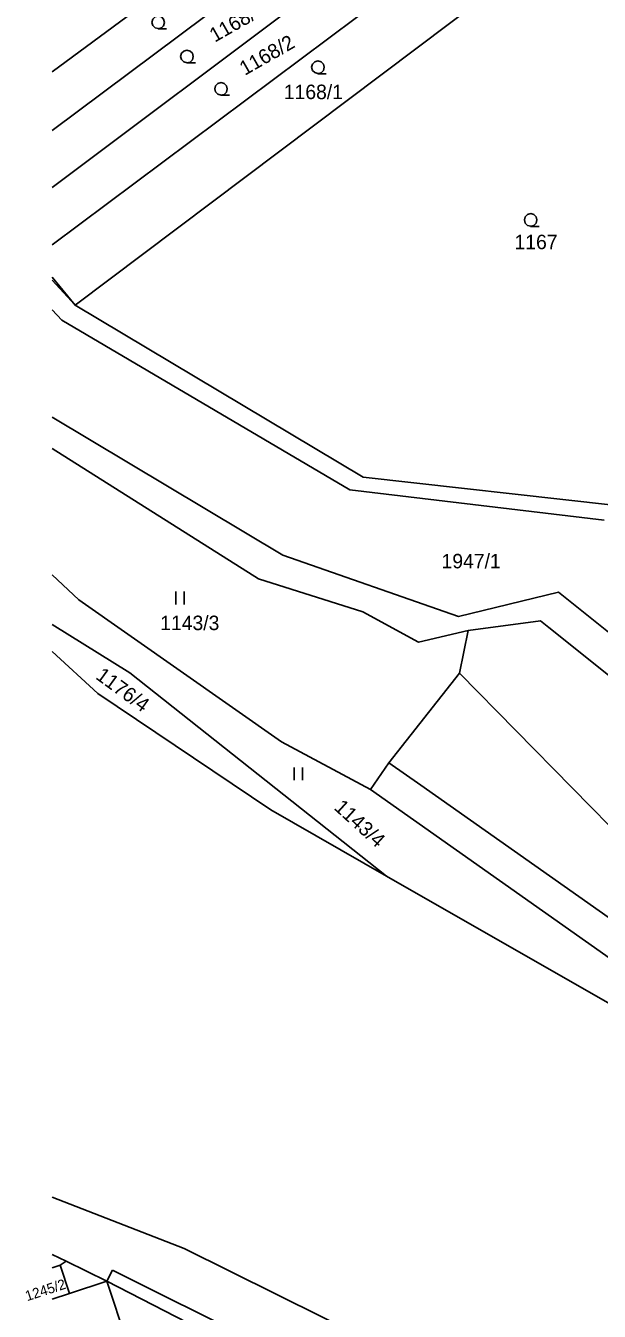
# Model space of a CAD drawing. Extents: x -621797 to -620972, y -1175539 to -1174697.
# Drawn here: x -621793.4 to -621726, y -1175130.5 to -1174979.5 of the extents above; entities that cross this region are included whole.
import ezdxf

# ---------------------------------------------------------------- set-up
doc = ezdxf.new("R2010")
doc.units = 0
for name, color, linetype in [('INZ mimo EON - nadz', 7, 'Continuous'), ('SDEL EON', 7, 'Continuous'), ('SDEL EON - popis', 7, 'Continuous'), ('Silnoproud EON', 7, 'Continuous'), ('Silnoproud EON - popis', 7, 'Continuous')]:
    doc.layers.add(name, color=color, linetype=linetype)

msp = doc.modelspace()

# ---------------------------------------------------------------- linework, layer by layer
at = {"layer": 'SDEL EON'}
for p, q in [((-621775.79, -1175045.98), (-621775.79, -1175047.48)), ((-621774.79, -1175047.48), (-621774.79, -1175045.98)), ((-621761.88, -1175066.65), (-621761.88, -1175068.15)), ((-621760.88, -1175068.15), (-621760.88, -1175066.65))]:
    msp.add_line(p, q, dxfattribs=at)
for points in [[(-621777.85, -1174979.84), (-621778.23, -1174979.74), (-621778.5, -1174979.47), (-621778.6, -1174979.1), (-621778.5, -1174978.73), (-621778.23, -1174978.46), (-621777.86, -1174978.36), (-621777.49, -1174978.46), (-621777.22, -1174978.73), (-621777.12, -1174979.11), (-621777.22, -1174979.49), (-621777.49, -1174979.76), (-621777.87, -1174979.86), (-621776.87, -1174979.86)], [(-621774.47, -1174983.85), (-621774.85, -1174983.75), (-621775.12, -1174983.48), (-621775.22, -1174983.11), (-621775.12, -1174982.74), (-621774.85, -1174982.47), (-621774.48, -1174982.37), (-621774.11, -1174982.47), (-621773.84, -1174982.74), (-621773.74, -1174983.12), (-621773.84, -1174983.5), (-621774.11, -1174983.77), (-621774.49, -1174983.87), (-621773.49, -1174983.87)], [(-621759.07, -1174985.11), (-621759.45, -1174985.01), (-621759.72, -1174984.74), (-621759.82, -1174984.37), (-621759.72, -1174984), (-621759.45, -1174983.73), (-621759.08, -1174983.63), (-621758.71, -1174983.73), (-621758.44, -1174984), (-621758.34, -1174984.38), (-621758.44, -1174984.76), (-621758.71, -1174985.03), (-621759.09, -1174985.13), (-621758.09, -1174985.13)], [(-621770.46, -1174987.65), (-621770.84, -1174987.55), (-621771.11, -1174987.28), (-621771.21, -1174986.91), (-621771.11, -1174986.54), (-621770.84, -1174986.27), (-621770.47, -1174986.17), (-621770.1, -1174986.27), (-621769.83, -1174986.54), (-621769.73, -1174986.92), (-621769.83, -1174987.3), (-621770.1, -1174987.57), (-621770.48, -1174987.67), (-621769.48, -1174987.67)], [(-621734.05, -1175003.05), (-621734.43, -1175002.95), (-621734.7, -1175002.68), (-621734.8, -1175002.31), (-621734.7, -1175001.94), (-621734.43, -1175001.67), (-621734.06, -1175001.57), (-621733.69, -1175001.67), (-621733.42, -1175001.94), (-621733.32, -1175002.32), (-621733.42, -1175002.7), (-621733.69, -1175002.97), (-621734.07, -1175003.07), (-621733.07, -1175003.07)]]:
    msp.add_lwpolyline(points, dxfattribs=at)
at = {"layer": 'SDEL EON - popis'}
for p, q in [((-621790.31, -1175009.025), (-621787.64, -1175012.33)), ((-621790.31, -1175012.859), (-621789.19, -1175014.1)), ((-621789.19, -1175014.1), (-621755.31, -1175034.04)), ((-621763.2, -1175041.7), (-621790.31, -1175025.479)), ((-621755.31, -1175034.04), (-621725.43, -1175037.6)), ((-621742.56, -1175048.92), (-621763.2, -1175041.7)), ((-621730.78, -1175046.05), (-621742.56, -1175048.92)), ((-621708.09, -1175064.2), (-621730.78, -1175046.05)), ((-621789.38, -1175125.13), (-621788.27, -1175128.45)), ((-621783.91, -1175127), (-621783.22, -1175125.7)), ((-621783.22, -1175125.7), (-621745.71, -1175144.4))]:
    msp.add_line(p, q, dxfattribs=at)
at = {"layer": 'Silnoproud EON'}
for p, q in [((-621744.96, -1174951.42), (-621790.31, -1174984.913)), ((-621742.03, -1174955.71), (-621790.31, -1174991.795)), ((-621739.05, -1174960.08), (-621790.31, -1174998.498)), ((-621735.95, -1174964.61), (-621790.31, -1175005.233)), ((-621787.64, -1175012.33), (-621731.98, -1174970.42)), ((-621787.64, -1175012.33), (-621790.31, -1175009.389)), ((-621753.77, -1175032.55), (-621787.64, -1175012.33)), ((-621790.31, -1175029.176), (-621766.07, -1175044.49)), ((-621724.31, -1175035.82), (-621753.77, -1175032.55)), ((-621790.31, -1175044.018), (-621787.2, -1175046.97)), ((-621766.07, -1175044.49), (-621753.78, -1175048.35)), ((-621787.2, -1175046.97), (-621763.37, -1175063.63)), ((-621753.78, -1175048.35), (-621747.25, -1175051.94)), ((-621781.19, -1175055.51), (-621790.31, -1175049.835)), ((-621741.43, -1175050.57), (-621732.91, -1175049.43)), ((-621732.91, -1175049.43), (-621731.94, -1175050.21)), ((-621731.94, -1175050.21), (-621710.01, -1175067.71)), ((-621747.25, -1175051.94), (-621741.43, -1175050.57)), ((-621741.43, -1175050.57), (-621742.42, -1175055.56)), ((-621784.96, -1175057.96), (-621790.31, -1175053.033)), ((-621751, -1175079.41), (-621781.19, -1175055.51)), ((-621750.75, -1175066.09), (-621742.42, -1175055.56)), ((-621742.42, -1175055.56), (-621712.54, -1175086.01)), ((-621764.61, -1175071.63), (-621784.96, -1175057.96)), ((-621763.37, -1175063.63), (-621752.9, -1175069.23)), ((-621752.9, -1175069.23), (-621750.75, -1175066.09)), ((-621750.75, -1175066.09), (-621746.97, -1175068.72)), ((-621717.9, -1175093.94), (-621752.9, -1175069.23)), ((-621746.97, -1175068.72), (-621715.17, -1175091.12)), ((-621751, -1175079.41), (-621764.61, -1175071.63)), ((-621706.61, -1175104.78), (-621751, -1175079.41)), ((-621790.31, -1175117.135), (-621774.82, -1175123.16)), ((-621790.31, -1175123.879), (-621788.69, -1175124.67)), ((-621774.82, -1175123.16), (-621749.91, -1175135.5)), ((-621789.38, -1175125.13), (-621790.31, -1175125.444)), ((-621788.69, -1175124.67), (-621789.38, -1175125.13)), ((-621788.69, -1175124.67), (-621783.91, -1175127)), ((-621783.91, -1175127), (-621788.27, -1175128.45)), ((-621783.91, -1175127), (-621777.64, -1175145.9)), ((-621783.91, -1175127), (-621766.01, -1175136.16)), ((-621788.27, -1175128.45), (-621790.31, -1175129.13))]:
    msp.add_line(p, q, dxfattribs=at)

# ---------------------------------------------------------------- texts
at = {"layer": 'INZ mimo EON - nadz'}
msp.add_text('1947/1', height=1.7, dxfattribs=at).set_placement((-621744.537, -1175043.25))
at = {"layer": 'Silnoproud EON - popis'}
for s, height, rotation, p in [('1168/3', 1.7, 29.67921, (-621771.209, -1174981.496)), ('1168/2', 1.7, 29.67921, (-621767.679, -1174985.396)), ('1176/4', 1.7, 324.00763, (-621785.322, -1175056.151)), ('1143/4', 1.7, 317.7051, (-621757.28, -1175071.494)), ('1245/2', 1.2, 17.99087, (-621793.276, -1175129.364))]:
    msp.add_text(s, height=height, rotation=rotation, dxfattribs=at).set_placement(p)
for s, p in [('1168/1', (-621763.087, -1174988.12)), ('1167', (-621735.957, -1175005.75)), ('1143/3', (-621777.617, -1175050.51))]:
    msp.add_text(s, height=1.7, dxfattribs=at).set_placement(p)

doc.saveas('drawing.dxf')
